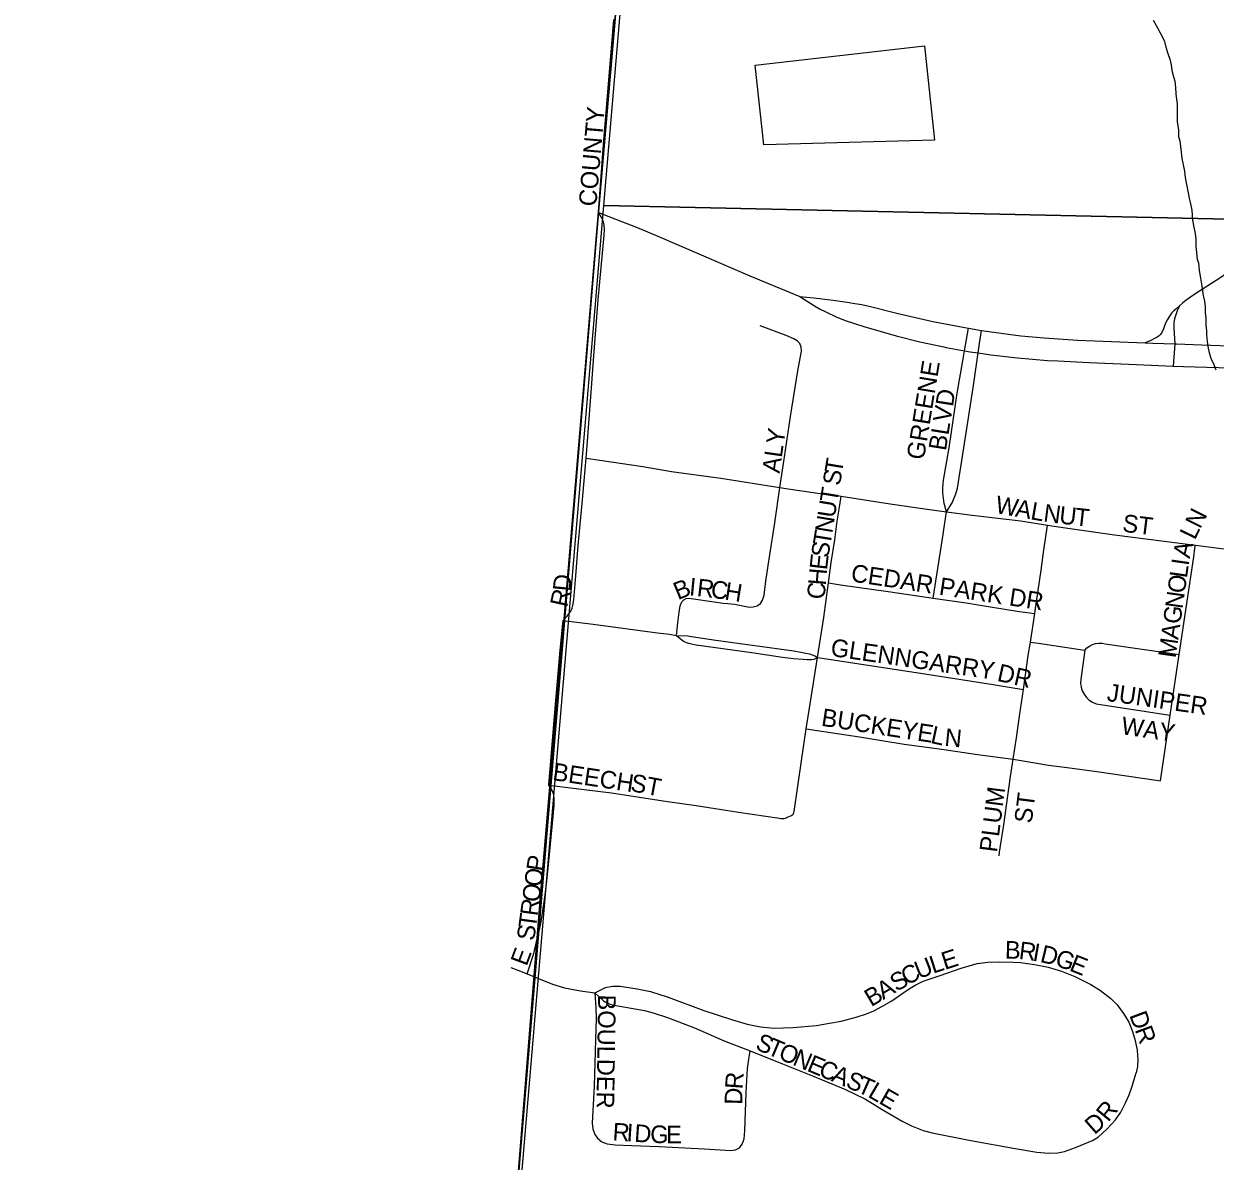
# Model space of a CAD drawing. Extents: x 1410790 to 1770854, y 448063 to 770588.
# Drawn here: x 1514996 to 1518372, y 619468 to 622690 of the extents above; entities that cross this region are included whole.
import ezdxf

# ---------------------------------------------------------------- set-up
doc = ezdxf.new("R2010")
doc.units = 0
for name, color, linetype in [('GM_X_Adjacent_County', 7, 'Continuous'), ('GM_X_City_Street', 7, 'Continuous'), ('GM_X_City_Street_Text', 7, 'Continuous'), ('GM_X_Corporation', 7, 'Continuous'), ('GM_X_County', 7, 'Continuous'), ('GM_X_Minor_Lake', 7, 'Continuous'), ('GM_X_Minor_River', 7, 'Continuous'), ('GM_X_Section', 7, 'Continuous'), ('GM_X_Township', 7, 'Continuous')]:
    doc.layers.add(name, color=color, linetype=linetype)

msp = doc.modelspace()

# ---------------------------------------------------------------- linework, layer by layer
at = {"layer": 'GM_X_Adjacent_County'}
msp.add_lwpolyline([(1517339.4, 630939.6), (1517193.5, 629397.8), (1517069.8, 628090.7), (1516949.9, 626822.9), (1516853.3, 625802.4), (1516836.6, 625625.7), (1516829.1, 625517.4), (1516813.1, 625302.8), (1516798.6, 625124.4), (1516799.3, 624956.3), (1516805.5, 624838), (1516815.9, 624733.7), (1516765.5, 623815), (1516721.1, 623275.7), (1516626.6, 622180.1), (1516525.9, 620993.2), (1516461.1, 620230.1), (1516373.4, 619132.2)], dxfattribs=at)
at = {"layer": 'GM_X_City_Street'}
for points in [[(1516624.7, 622155.6), (1516639.7, 622360.7), (1516647.9, 622462.2), (1516654.5, 622542.8), (1516662.6, 622632.4), (1516668.1, 622702.4)], [(1516589.2, 621460), (1516592.2, 621495.1), (1516604.5, 621658.8), (1516611.6, 621749.4), (1516623.4, 621908.4), (1516640.5, 622091.4), (1516641.5, 622107.1), (1516640.5, 622120), (1516638.6, 622127.9), (1516635.9, 622136.1), (1516632.3, 622143.7), (1516624.7, 622155.6)], [(1516624.7, 622155.6), (1516734, 622113.1), (1516785.6, 622091.8), (1516915, 622036.1), (1517053.6, 621976.7), (1517195.1, 621917.8)], [(1518438.2, 622007.7), (1518422.2, 621994.9), (1518388.2, 621971.4), (1518314, 621924), (1518292.4, 621909.5), (1518284.9, 621903.8), (1518278.8, 621898.7), (1518271, 621890.9)], [(1517195.1, 621917.8), (1517236.1, 621891.4), (1517250.7, 621882.9), (1517268.2, 621873.9), (1517297.7, 621860.4), (1517323, 621850), (1517376.5, 621833), (1517468.2, 621806.6), (1517535.3, 621789.6), (1517602.8, 621774.9), (1517609.9, 621773.6)], [(1517195.1, 621917.8), (1517235, 621913.8), (1517289.1, 621907.4), (1517329.5, 621901.8), (1517350.4, 621898.2), (1517370.3, 621894.6), (1517395.3, 621889.6), (1517473.5, 621869.6), (1517571.5, 621847.1), (1517662.4, 621829.6), (1517672.6, 621827.9)], [(1518271, 621890.9), (1518260.2, 621882.2), (1518254.8, 621877.1), (1518248.4, 621870.8), (1518242.2, 621862.3), (1518236.5, 621853), (1518232.4, 621844.4), (1518228.3, 621834.7), (1518225, 621825.7), (1518220.5, 621815.8), (1518216.6, 621810.3), (1518213, 621806.4), (1518207, 621802.2), (1518200.1, 621798.3), (1518189.6, 621793.5), (1518173.5, 621786.5)], [(1518271, 621890.9), (1518264.4, 621876.8), (1518260.2, 621866.2), (1518256.6, 621854.5), (1518254.8, 621843.4), (1518254.2, 621835.3), (1518254.2, 621827.9), (1518257.1, 621783.8)], [(1517138.6, 621376.7), (1517147.6, 621438.2), (1517168.9, 621577.6), (1517188.9, 621707.2), (1517199.7, 621762.8), (1517199, 621773.9), (1517194.7, 621784.1), (1517187.1, 621792), (1517178.2, 621797.7), (1517156.4, 621807.5), (1517082.4, 621834.7)], [(1517661.7, 621764.1), (1517667.1, 621796), (1517672.6, 621827.9)], [(1517672.6, 621827.9), (1517709.4, 621821.8)], [(1517700.4, 621757.8), (1517704.2, 621784.9), (1517709.4, 621821.8)], [(1517709.4, 621821.8), (1517730.3, 621818.3), (1517821.5, 621806.6), (1517886.9, 621800.5), (1517981.9, 621794.1), (1518077.7, 621789.9), (1518173.5, 621786.5)], [(1517610.3, 621307.3), (1517604.1, 621331.5), (1517600.1, 621361.1), (1517599.9, 621375.1), (1517602.4, 621397.2), (1517618.2, 621489), (1517641, 621643.4), (1517656.6, 621735.1), (1517661.7, 621764.1)], [(1517609.9, 621773.6), (1517661.7, 621764.1)], [(1517661.7, 621764.1), (1517677.3, 621761.2), (1517700.4, 621757.8)], [(1518173.5, 621786.5), (1518195.2, 621785.7), (1518257.1, 621783.8)], [(1518257.1, 621783.8), (1518253.1, 621720.2)], [(1518257.1, 621783.8), (1518262.6, 621783.6), (1518333, 621781.2), (1518438, 621777), (1518565.7, 621769.8), (1518650.7, 621763.4), (1518768.2, 621751.6), (1518852.6, 621737.1), (1518857.4, 621736.3)], [(1517610.3, 621307.3), (1517626.5, 621332.9), (1517637.1, 621358.7), (1517641.4, 621374.8), (1517664.3, 621519.6), (1517687.4, 621665.1), (1517700.4, 621757.8)], [(1517700.4, 621757.8), (1517736, 621752.5), (1517811.3, 621744.1), (1517896.6, 621736.8), (1517926.2, 621735.3)], [(1517926.2, 621735.3), (1518014.8, 621730.6), (1518149.3, 621724.8), (1518253.1, 621720.2)], [(1518253.1, 621720.2), (1518282.4, 621719.7), (1518414, 621715.5), (1518418.3, 621715.3)], [(1516524.8, 621000.2), (1516536, 621011.9), (1516545.9, 621025.9), (1516550, 621034.5), (1516552.2, 621042.1), (1516554.5, 621057.9), (1516560.2, 621126.3), (1516567.2, 621212.1), (1516578.1, 621331), (1516589.2, 621460)], [(1516589.2, 621460), (1516627.9, 621454.1), (1516750.6, 621435.6), (1516831.4, 621422.1), (1516971, 621402.8), (1517138.6, 621376.7)], [(1516845.6, 620957.7), (1516848.9, 620993.4), (1516852.7, 621022.9), (1516856.2, 621041.5), (1516860.9, 621052.3), (1516866.3, 621058.5), (1516873, 621062.1), (1516880.9, 621062.8), (1516958.6, 621051.2), (1516978.2, 621048.8), (1516990.8, 621048.2), (1517010, 621046.1), (1517052.1, 621037.7), (1517063.1, 621038), (1517073.9, 621041.5), (1517083.1, 621048.3), (1517089.5, 621057.6), (1517094, 621071.3), (1517098.4, 621110.8), (1517105.4, 621155.9), (1517123.8, 621276), (1517138.6, 621376.7)], [(1517138.6, 621376.7), (1517155.6, 621374), (1517246.4, 621360.6), (1517301.6, 621353.5), (1517312, 621351.9)], [(1517276.4, 621106.1), (1517284.1, 621163.9), (1517293.8, 621228.7), (1517300.8, 621280.8), (1517307.9, 621326.3), (1517312, 621351.9)], [(1517312, 621351.9), (1517450.5, 621330.7), (1517549.3, 621316), (1517610.3, 621307.3)], [(1517572.7, 621063.4), (1517585.7, 621147.4), (1517600.7, 621243.4), (1517602.9, 621258), (1517610.3, 621307.3)], [(1517610.3, 621307.3), (1517683.3, 621298.6), (1517821, 621281.9), (1517896.5, 621270.1)], [(1517860.7, 621019.5), (1517861.8, 621026.7), (1517878.3, 621142.3), (1517886.5, 621200), (1517893.6, 621249.6), (1517896.5, 621270.1)], [(1517896.5, 621270.1), (1517934.5, 621264.1), (1518086.5, 621242.9), (1518315.9, 621212.8)], [(1518269.9, 620903.6), (1518311, 621179.8), (1518314.6, 621204.5), (1518315.9, 621212.8)], [(1518315.9, 621212.8), (1518617.9, 621174.2)], [(1517245.2, 620894.7), (1517263.4, 621007.8), (1517276.4, 621106.1)], [(1517276.4, 621106.1), (1517310.2, 621101.2), (1517445.4, 621081.7), (1517502.6, 621073.3), (1517572.7, 621063.4)], [(1517572.7, 621063.4), (1517672.6, 621048.4), (1517694.8, 621045.5), (1517816.8, 621024.9), (1517832.9, 621022.9), (1517860.7, 621019.5)], [(1517848.2, 620938.5), (1517860.7, 621019.5)], [(1516483.8, 620533), (1516500.7, 620740), (1516516.3, 620915.4), (1516524.8, 621000.2)], [(1516524.8, 621000.2), (1516609, 620989), (1516791.9, 620964.7), (1516825.3, 620960.6), (1516845.6, 620957.7)], [(1516845.6, 620957.7), (1516877.3, 620956.1), (1516900.4, 620952.5), (1516957.4, 620943.7), (1517177.6, 620913.4), (1517197.7, 620910.4), (1517212.3, 620907.5), (1517222.1, 620905.1), (1517237.4, 620899.4), (1517245.2, 620894.7)], [(1516845.6, 620957.7), (1516865.5, 620941.5), (1516873, 620937.2), (1516883.5, 620934.7), (1516900.9, 620931.2), (1517058.7, 620908.8), (1517145.4, 620895.8), (1517177.3, 620891.9), (1517204.8, 620889.8), (1517215.3, 620889.3), (1517228, 620889.5), (1517235.5, 620890.5), (1517245.2, 620894.7)], [(1517828.4, 620804), (1517842.3, 620900.7), (1517848.2, 620938.5)], [(1517848.2, 620938.5), (1517871, 620935.4), (1517988.9, 620917.9), (1518002, 620915.9)], [(1518002, 620915.9), (1518008.6, 620922.2), (1518016.1, 620927.4), (1518024.3, 620931.4), (1518033, 620934.1), (1518042.1, 620935.3), (1518051.2, 620935.1), (1518060.2, 620933.5), (1518269.9, 620903.6)], [(1517213.3, 620693.1), (1517222.2, 620751.7), (1517245.2, 620894.7)], [(1517245.2, 620894.7), (1517270.3, 620890.9), (1517549, 620848.7), (1517743.2, 620818.2), (1517788.5, 620810.6), (1517828.4, 620804)], [(1518002, 620915.9), (1517998.3, 620888.1), (1517991.1, 620833), (1517990.6, 620822), (1517992, 620811), (1517995.3, 620800.4), (1518000.3, 620790.6), (1518007, 620781.8), (1518015.1, 620774.3), (1518024.4, 620768.2), (1518034.6, 620763.9), (1518244.3, 620731.4)], [(1518244.3, 620731.4), (1518269.9, 620903.6)], [(1517799.2, 620606.4), (1517808.5, 620667.4), (1517817.5, 620729), (1517828.4, 620804)], [(1518216.6, 620545.1), (1518244.3, 620731.4)], [(1517162.1, 620443), (1517167, 620445), (1517171.4, 620447.6), (1517175.9, 620451), (1517177.6, 620454.5), (1517178.8, 620459), (1517199.6, 620602.5), (1517213.3, 620693.1)], [(1517213.3, 620693.1), (1517244.2, 620688.4), (1517364.2, 620670.1), (1517490.4, 620649.8), (1517597.6, 620635.3), (1517698.1, 620619.8), (1517799.2, 620606.4)], [(1517759.4, 620333.4), (1517760.7, 620343.1), (1517773.4, 620420.8), (1517791.6, 620557.3), (1517799.2, 620606.4)], [(1517799.2, 620606.4), (1517827.9, 620601.8), (1517899.9, 620590.3), (1517952.3, 620583.2), (1518036.5, 620572), (1518204.4, 620547), (1518216.6, 620545.1)], [(1516422, 619998.2), (1516441.1, 620056), (1516452.9, 620106.2), (1516457.9, 620127.6), (1516461.7, 620146.5), (1516465.9, 620170.9), (1516472.7, 620216), (1516477.2, 620252.7), (1516483.7, 620316.5), (1516493.7, 620415.4), (1516499.2, 620475.5), (1516499.3, 620494.7), (1516497.8, 620506), (1516495.5, 620513.2), (1516491.4, 620521.8), (1516483.8, 620533)], [(1516483.8, 620533), (1516661.8, 620511.3), (1516820.1, 620487.2), (1516901, 620475.2), (1517020.8, 620457), (1517137.2, 620439.5), (1517141, 620438.9), (1517143.9, 620438.5), (1517149.9, 620438.9), (1517153.9, 620439.6), (1517162.1, 620443)], [(1516376.4, 620017), (1516396.1, 620008.9), (1516422, 619998.2)], [(1516614, 619945), (1516644.5, 619959.9), (1516664.2, 619963.6), (1516686.3, 619963.6), (1516733.9, 619956.5), (1516772.3, 619948.2), (1516822.1, 619932.2), (1516923.3, 619894.4), (1517001.3, 619869.3), (1517045.5, 619856), (1517083.7, 619848.2), (1517122.6, 619844.6), (1517175.1, 619847), (1517242.1, 619852.4), (1517279.2, 619858.4), (1517312, 619864.3), (1517354.4, 619876.3), (1517384.3, 619885.2), (1517404.6, 619894.2), (1517427.1, 619906), (1517455.6, 619922), (1517490.4, 619946.6), (1517512.3, 619961), (1517523.6, 619967.5), (1517544.1, 619977.7), (1517592.3, 619994), (1517652.1, 620014.3), (1517697.5, 620027.5), (1517728, 620031.7), (1517760.8, 620032.3), (1517799.1, 620031.5), (1517820.6, 620030.5), (1517840.4, 620028), (1517860.1, 620025.1), (1517898.9, 620017.3), (1517936.5, 620006), (1517974.2, 619991.1), (1518019, 619968.3), (1518046.5, 619951.6), (1518075.8, 619928.9), (1518094.3, 619910.4), (1518112.3, 619886.5), (1518127.2, 619861.9), (1518137.9, 619835), (1518145.1, 619809.4), (1518150.5, 619782.5), (1518151.9, 619767.6), (1518153, 619756.1), (1518151.7, 619736.5), (1518147.5, 619717.9)], [(1516422, 619998.2), (1516454.2, 619985), (1516493.9, 619969.4), (1516528.6, 619959), (1516573.6, 619950.4), (1516614, 619945)], [(1516614, 619945), (1516617, 619902.6), (1516617.7, 619873.4), (1516616.4, 619811.2), (1516612, 619680.2), (1516606.4, 619575.3), (1516608.4, 619559), (1516613.9, 619543.7), (1516621.6, 619533.2), (1516634.3, 619523.1), (1516649.4, 619517.2), (1516672.2, 619514), (1516718.1, 619512.5), (1516796.6, 619509.2), (1516924.2, 619502.6), (1516999.5, 619497.7), (1517012.4, 619500), (1517023.8, 619505.9), (1517032, 619515.7), (1517037.3, 619530.9), (1517039.5, 619553.8), (1517043.2, 619662.1), (1517047.1, 619730.8), (1517049.9, 619750.3), (1517054, 619780.1)], [(1516614, 619945), (1516638.7, 619922.1), (1516649.9, 619915.1), (1516663.7, 619910.6), (1516754.4, 619894.3), (1516779.8, 619888.4), (1516820.2, 619874.8), (1516896.7, 619845.5), (1516981, 619809), (1517054, 619780.1)], [(1517054, 619780.1), (1517145.6, 619743.9), (1517230.9, 619709.9), (1517324.8, 619670.9), (1517380.7, 619643.5), (1517428.4, 619614.6), (1517484.8, 619580.9), (1517511.1, 619567.8), (1517544.7, 619554.9), (1517569.9, 619547.7), (1517679.4, 619526.6), (1517805.3, 619504.1), (1517866.7, 619493.5), (1517899.4, 619490.7), (1517925.6, 619491.8), (1517944.9, 619495.3), (1517975.7, 619506.5), (1518024.4, 619526.2), (1518041.1, 619536.4), (1518065, 619558.7), (1518089.5, 619585.3), (1518104.6, 619606.7), (1518117.9, 619632.9), (1518127.8, 619655.8), (1518136.1, 619677.9), (1518141.9, 619699.4), (1518147.5, 619717.9)]]:
    msp.add_lwpolyline(points, dxfattribs=at)
at = {"layer": 'GM_X_Corporation'}
for points in [[(1516399, 619440.9), (1516626.6, 622180.1), (1516721.1, 623275.7), (1516765.5, 623815), (1516815.9, 624733.7), (1516805.5, 624838), (1516799.3, 624956.3), (1516798.6, 625124.4), (1516813.1, 625302.8), (1516829.1, 625517.4), (1516836.6, 625625.7), (1517842.6, 636258), (1517955.8, 637494.3), (1518046.7, 638486.5), (1518156.8, 639578.3), (1518331.8, 641513.1), (1518983.8, 648721.9)], [(1514145.2, 633864.2), (1515638.4, 633722.2), (1515727.3, 634707.3), (1515831.7, 635865.4), (1515911.8, 635861.8), (1515961.8, 636458.2), (1517842.6, 636258), (1516836.6, 625625.7), (1516829.1, 625517.4), (1516813.1, 625302.8), (1516798.6, 625124.4), (1516799.3, 624956.3), (1516805.5, 624838), (1516815.9, 624733.7), (1516765.5, 623815), (1516721.1, 623275.7), (1516626.6, 622180.1), (1516399, 619440.9)]]:
    msp.add_lwpolyline(points, dxfattribs=at)
at = {"layer": 'GM_X_County'}
msp.add_lwpolyline([(1517339.4, 630939.6), (1517193.5, 629397.8), (1517069.8, 628090.7), (1516949.9, 626822.9), (1516853.3, 625802.4), (1516836.6, 625625.7), (1516829.1, 625517.4), (1516813.1, 625302.8), (1516798.6, 625124.4), (1516799.3, 624956.3), (1516805.5, 624838), (1516815.9, 624733.7), (1516765.5, 623815), (1516721.1, 623275.7), (1516626.6, 622180.1), (1516525.9, 620993.2), (1516461.1, 620230.1), (1516373.4, 619132.2)], dxfattribs=at)
at = {"layer": 'GM_X_Minor_Lake'}
msp.add_lwpolyline([(1517068.5, 622573.3), (1517548.5, 622628), (1517576.6, 622360.4), (1517093.4, 622347.9), (1517068.5, 622573.3)], dxfattribs=at)
at = {"layer": 'GM_X_Minor_River'}
for points in [[(1518196.5, 622701.1), (1518208.3, 622678.9), (1518216.2, 622664.8), (1518222.1, 622652.7), (1518228, 622640.6), (1518231.9, 622624.5), (1518237.7, 622606.4), (1518243.6, 622590.3), (1518247.4, 622574.2), (1518249.3, 622558.1), (1518253.2, 622544), (1518257, 622527.9), (1518258.9, 622509.8), (1518260.7, 622491.8), (1518262.6, 622475.7), (1518264.5, 622463.6), (1518264.4, 622451.6), (1518264, 622413.5), (1518265.9, 622401.4), (1518267.8, 622389.3), (1518267.7, 622371.3), (1518271.6, 622359.2), (1518273.4, 622343.1), (1518275.3, 622327), (1518277.1, 622309), (1518281, 622290.9)], [(1518281, 622290.9), (1518284.8, 622272.8), (1518286.6, 622254.7), (1518290.5, 622234.6), (1518294.3, 622216.5), (1518298.1, 622196.4), (1518302, 622180.3), (1518305.8, 622162.2), (1518307.6, 622134), (1518311.4, 622113.9), (1518315.3, 622095.8), (1518317.1, 622079.8), (1518317, 622061.7), (1518318.8, 622041.6), (1518320.6, 622023.5), (1518324.5, 622013.4), (1518326.3, 621991.3), (1518330.1, 621969.2), (1518334, 621947.1), (1518337.7, 621921), (1518341.6, 621904.9), (1518343.5, 621888.8), (1518343.3, 621872.8), (1518345.2, 621856.7), (1518345.1, 621846.7), (1518345, 621836.6), (1518346.9, 621820.5), (1518346.8, 621810.5), (1518348.6, 621798.4), (1518350.5, 621776.3), (1518354.3, 621758.2), (1518360.1, 621740.1), (1518366.1, 621730), (1518373.9, 621709.9)]]:
    msp.add_lwpolyline(points, dxfattribs=at)
at = {"layer": 'GM_X_Section'}
for points in [[(1516936.9, 625665.1), (1522174.5, 625186.4), (1522801.4, 625129.5), (1522551.9, 622046.6), (1516639.8, 622176)], [(1522551.9, 622046.6), (1522119.9, 616619.5), (1516186.2, 616821.5), (1516639.8, 622176)]]:
    msp.add_lwpolyline(points, close=True, dxfattribs=at)
at = {"layer": 'GM_X_Township'}
msp.add_lwpolyline([(1516373.4, 619132.2), (1516461.1, 620230.1), (1516525.9, 620993.2), (1516626.6, 622180.1), (1516721.1, 623275.7), (1516765.5, 623815), (1516815.9, 624733.7), (1516805.5, 624838), (1516799.3, 624956.3), (1516798.6, 625124.4), (1516813.1, 625302.8), (1516829.1, 625517.4), (1516836.6, 625625.7), (1516853.3, 625802.4), (1516949.9, 626822.9), (1517069.8, 628090.7), (1517193.5, 629397.8), (1517339.4, 630939.6)], dxfattribs=at)

# ---------------------------------------------------------------- texts
at = {"layer": 'GM_X_City_Street_Text'}
for s, rotation, p in [('COUNTY', 85.0736, (1516618.1, 622171.6)), ('GREENE', 80.7045, (1517546.4, 621452.9)), ('BLVD', 81.0281, (1517608.8, 621478.9)), ('ALY', 81.8704, (1517137.4, 621415.3)), ('T', 80.8195, (1517314.2, 621414.6)), ('S', 80.8195, (1517308.6, 621379.9)), ('T', 80.8195, (1517300.9, 621332.1)), ('U', 80.8035, (1517293.8, 621288.6)), ('W', 350.0305, (1517746.7, 621304.5)), ('A', 350.0275, (1517803.1, 621294.6)), ('L', 350.1365, (1517846.5, 621286.9)), ('N', 352.4009, (1517883.3, 621280.6)), ('U', 353.6158, (1517928.1, 621274.6)), ('N', 80.8133, (1517286.8, 621245.2)), ('T', 353.6379, (1517971.9, 621269.7)), ('ST', 352.8657, (1518107.1, 621251.7)), ('N', 63.4349, (1518329.4, 621257.3)), ('T', 80.7937, (1517281.2, 621210.4)), ('L', 63.9116, (1518314, 621225.8)), ('S', 81.2248, (1517275.8, 621175.7)), ('A', 76.2871, (1518299.4, 621173.6)), ('E', 83.4848, (1517271.9, 621141.3)), ('CEDAR PARK DR', 351.3689, (1517337.6, 621110.8)), ('I', 81.9101, (1518296.5, 621153.1)), ('D', 84.7564, (1516544.8, 621080.8)), ('H', 85.1786, (1517268.2, 621097.8)), ('O', 81.907, (1518285.4, 621074.6)), ('L', 81.9245, (1518291.6, 621118.2)), ('R', 77.6661, (1516535.4, 621035.5)), ('B', 22.4237, (1516849.7, 621057)), ('I', 354.5286, (1516880, 621071.1)), ('R', 353.2575, (1516901.7, 621069.1)), ('C', 352.9638, (1516940.9, 621064.4)), ('H', 350.9796, (1516979.8, 621059.6)), ('C', 85.1738, (1517264.9, 621058.3)), ('N', 81.9198, (1518279.2, 621031.1)), ('G', 81.907, (1518273, 620987.5)), ('A', 81.9198, (1518266.8, 620943.9)), ('GLENNGARRY', 351.701, (1517280.1, 620899.7)), ('M', 81.9034, (1518259.4, 620891.7)), ('DR', 347.4673, (1517751.5, 620829.1)), ('JUNIPER', 351.8707, (1518063.2, 620772.1)), ('BUCKEYE', 351.2521, (1517253.7, 620701.7)), ('WAY', 351.3823, (1518103.2, 620678.2)), ('L', 347.889, (1517563, 620653)), ('N', 354.3068, (1517603.4, 620644.7)), ('BEECH', 351.3474, (1516492.5, 620547.7)), ('ST', 349.3733, (1516712.8, 620516.8)), ('PLUM', 82.6978, (1517753.3, 620341.2)), ('ST', 82.88, (1517851.9, 620423.3)), ('P', 81.2248, (1516469, 620286.8)), ('O', 82.2082, (1516463, 620243.4)), ('O', 82.2082, (1516457.1, 620199.8)), ('R', 82.2031, (1516451.7, 620160.6)), ('T', 82.2191, (1516446.9, 620125.7)), ('S', 82.2041, (1516442.2, 620090.8)), ('B', 358.7858, (1517775.6, 620041.8)), ('R', 352.89, (1517813.9, 620041.1)), ('I', 350.2035, (1517852.5, 620036.3)), ('D', 346.523, (1517873.4, 620032.7)), ('E', 69.4529, (1516420.7, 620018.1)), ('U', 21.3184, (1517531.8, 619983)), ('L', 17.7697, (1517572, 619998.8)), ('E', 17.5708, (1517605.5, 620009.5)), ('G', 341.0122, (1517915, 620022.8)), ('E', 338.1682, (1517955.9, 620008.7)), ('C', 29.5039, (1517499, 619964.3)), ('A', 30.5664, (1517431.1, 619924.2)), ('S', 30.5962, (1517469, 619946.6)), ('B', 30.5764, (1517397, 619904)), ('BOULDER', 269.1326, (1516623.7, 619940.2)), ('D', 290.4844, (1518127.9, 619881.7)), ('R', 290.0786, (1518143.3, 619840.6)), ('S', 337.2194, (1517066.3, 619786)), ('T', 337.2507, (1517098.8, 619772.4)), ('O', 337.2406, (1517131.2, 619758.8)), ('N', 337.2204, (1517171.8, 619741.8)), ('E', 337.2507, (1517212.4, 619724.7)), ('C', 337.2335, (1517244.8, 619711.1)), ('R', 85.8434, (1517032.7, 619670.6)), ('A', 337.2204, (1517281.4, 619695.8)), ('S', 337.2591, (1517322, 619678.7)), ('T', 336.2955, (1517354.2, 619665.2)), ('D', 88.5903, (1517031.7, 619627.3)), ('L', 329.6079, (1517385.1, 619651.7)), ('E', 330.2364, (1517416, 619633.6)), ('R', 50.7709, (1518068.9, 619576.5)), ('R', 356.2328, (1516663.3, 619527)), ('I', 356.2383, (1516702.8, 619524.4)), ('D', 356.2383, (1516724.8, 619522.9)), ('G', 357.831, (1516770.2, 619520)), ('E', 359.914, (1516816.2, 619518.3)), ('D', 41.2959, (1518029.7, 619541.1))]:
    msp.add_text(s, height=50, rotation=rotation, dxfattribs=at).set_placement(p)

doc.saveas('drawing.dxf')
